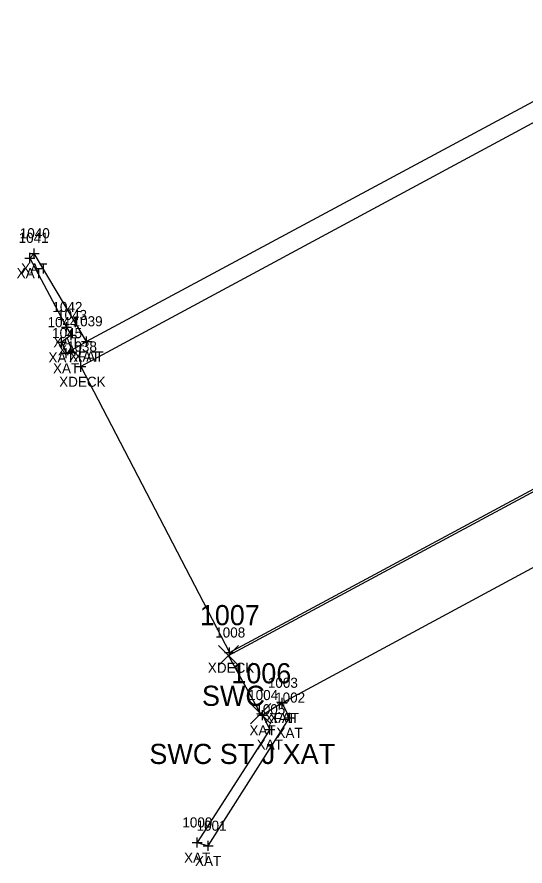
# Model space of a CAD drawing. Extents: x 1635588 to 1637550, y 621583 to 623638.
# Drawn here: x 1636318.7 to 1636369.1, y 623110.9 to 623195.1 of the extents above; entities that cross this region are included whole.
import ezdxf

# ---------------------------------------------------------------- set-up
doc = ezdxf.new("R2010")
doc.units = 0
for name, color, linetype in [('B_A', 7, 'Continuous'), ('B_I', 7, 'Continuous'), ('B_TIC', 7, 'Continuous'), ('BELB', 7, 'Continuous'), ('BF', 7, 'Continuous'), ('BSUBM', 7, 'Continuous'), ('R_A', 7, 'Continuous'), ('R_I', 7, 'Continuous'), ('R_TIC', 7, 'Continuous'), ('RSW', 7, 'Continuous')]:
    doc.layers.add(name, color=color, linetype=linetype)

msp = doc.modelspace()

# ---------------------------------------------------------------- linework, layer by layer
at = {"layer": 'B_TIC'}
for p, q in [((1636320.413, 623171.69), (1636320.489, 623171.69)), ((1636319.973, 623171.231), (1636320.049, 623171.231)), ((1636323.607, 623164.377), (1636323.683, 623164.377)), ((1636324.067, 623163.583), (1636324.142, 623163.583)), ((1636323.126, 623162.873), (1636323.201, 623162.873)), ((1636325.614, 623162.961), (1636325.69, 623162.961)), ((1636325.614, 623162.961), (1636325.69, 623162.961)), ((1636323.576, 623161.791), (1636323.651, 623161.791)), ((1636325.047, 623160.457), (1636325.122, 623160.457)), ((1636339.788, 623132.094), (1636339.864, 623132.094)), ((1636345.01, 623127.108), (1636345.086, 623127.108)), ((1636345.01, 623127.108), (1636345.086, 623127.108)), ((1636343.057, 623125.889), (1636343.132, 623125.889)), ((1636345.732, 623125.637), (1636345.807, 623125.637)), ((1636343.765, 623124.477), (1636343.84, 623124.477)), ((1636336.573, 623113.259), (1636336.649, 623113.259)), ((1636337.656, 623112.931), (1636337.732, 623112.931))]:
    msp.add_line(p, q, dxfattribs=at)
for points in [[(1636319.91, 623171.69), (1636320.91, 623171.69)], [(1636319.97, 623170.731), (1636319.97, 623171.731)], [(1636320.41, 623171.19), (1636320.41, 623172.19)], [(1636319.47, 623171.231), (1636320.47, 623171.231)], [(1636323.604, 623163.877), (1636323.604, 623164.877)], [(1636323.104, 623164.377), (1636324.104, 623164.377)], [(1636324.063, 623163.083), (1636324.063, 623164.083)], [(1636323.122, 623162.373), (1636323.122, 623163.373)], [(1636323.563, 623163.583), (1636324.563, 623163.583)], [(1636325.611, 623162.461), (1636325.611, 623163.461)], [(1636325.611, 623162.461), (1636325.611, 623163.461)], [(1636322.622, 623162.873), (1636323.622, 623162.873)], [(1636325.111, 623162.961), (1636326.111, 623162.961)], [(1636325.111, 623162.961), (1636326.111, 623162.961)], [(1636323.072, 623161.791), (1636324.072, 623161.791)], [(1636323.572, 623161.291), (1636323.572, 623162.291)], [(1636325.043, 623159.957), (1636325.043, 623160.957)], [(1636324.543, 623160.457), (1636325.543, 623160.457)], [(1636339.285, 623132.094), (1636340.285, 623132.094)], [(1636339.785, 623131.594), (1636339.785, 623132.594)], [(1636344.507, 623127.108), (1636345.507, 623127.108)], [(1636344.507, 623127.108), (1636345.507, 623127.108)], [(1636345.007, 623126.608), (1636345.007, 623127.608)], [(1636345.007, 623126.608), (1636345.007, 623127.608)], [(1636343.053, 623125.389), (1636343.053, 623126.389)], [(1636342.553, 623125.889), (1636343.553, 623125.889)], [(1636345.228, 623125.637), (1636346.228, 623125.637)], [(1636345.728, 623125.137), (1636345.728, 623126.137)], [(1636343.261, 623124.477), (1636344.261, 623124.477)], [(1636343.761, 623123.977), (1636343.761, 623124.977)], [(1636336.57, 623112.759), (1636336.57, 623113.759)], [(1636336.07, 623113.259), (1636337.07, 623113.259)], [(1636337.153, 623112.931), (1636338.153, 623112.931)], [(1636337.653, 623112.431), (1636337.653, 623113.431)]]:
    msp.add_lwpolyline(points, dxfattribs=at)
at = {"layer": 'BELB'}
msp.add_lwpolyline([(1636339.785, 623132.094), (1636403.647, 623166.459), (1636403.692, 623166.437), (1636388.517, 623194.676), (1636325.043, 623160.457), (1636339.785, 623132.094)], dxfattribs=at)
at = {"layer": 'BF'}
for points in [[(1636385.549, 623195.138), (1636325.611, 623162.961)], [(1636345.007, 623127.108), (1636404.932, 623159.451)]]:
    msp.add_lwpolyline(points, dxfattribs=at)
at = {"layer": 'BSUBM'}
for points in [[(1636325.611, 623162.961), (1636320.41, 623171.69), (1636319.97, 623171.231), (1636323.604, 623164.377), (1636324.063, 623163.583), (1636323.122, 623162.873), (1636323.572, 623161.791), (1636325.611, 623162.961)], [(1636336.57, 623113.259), (1636337.653, 623112.931), (1636345.728, 623125.637), (1636345.007, 623127.108), (1636343.053, 623125.889), (1636343.761, 623124.477), (1636336.57, 623113.259)]]:
    msp.add_lwpolyline(points, dxfattribs=at)
at = {"layer": 'R_TIC'}
for points in [[(1636338.684, 623130.815), (1636340.684, 623132.815)], [(1636340.684, 623130.815), (1636338.684, 623132.815)], [(1636341.862, 623125.048), (1636343.862, 623127.048)], [(1636343.862, 623125.048), (1636341.862, 623127.048)]]:
    msp.add_lwpolyline(points, dxfattribs=at)
at = {"layer": 'RSW'}
for points in [[(1636342.862, 623126.048), (1636339.684, 623131.815), (1636403.698, 623166.218)], [(1636343.053, 623125.889), (1636342.862, 623126.048)]]:
    msp.add_lwpolyline(points, dxfattribs=at)

# ---------------------------------------------------------------- texts
at = {"layer": 'B_A'}
for s, p in [('XAT', (1636318.675, 623169.231)), ('XAT', (1636319.115, 623169.69)), ('XAT', (1636322.309, 623162.377)), ('XAT', (1636322.768, 623161.583)), ('XAT', (1636321.827, 623160.873)), ('XFAT', (1636323.867, 623160.961)), ('XAT', (1636324.315, 623160.961)), ('XAT', (1636322.277, 623159.791)), ('XDECK', (1636322.886, 623158.457)), ('XDECK', (1636337.627, 623130.094)), ('XFAT', (1636343.263, 623125.108)), ('XAT', (1636343.711, 623125.108)), ('XAT', (1636341.758, 623123.889)), ('XAT', (1636344.433, 623123.637)), ('XAT', (1636342.466, 623122.477)), ('XAT', (1636335.274, 623111.259)), ('XAT', (1636336.358, 623110.931))]:
    msp.add_text(s, height=1, dxfattribs=at).set_placement(p)
at = {"layer": 'B_I'}
for s, p in [('1040', (1636318.981, 623173.19)), ('1041', (1636318.868, 623172.731)), ('1042', (1636322.218, 623165.877)), ('1043', (1636322.678, 623165.083)), ('1044', (1636321.737, 623164.373)), ('1039', (1636324.221, 623164.461)), ('1039', (1636324.221, 623164.461)), ('1045', (1636322.187, 623163.291)), ('1038', (1636323.658, 623161.957)), ('1008', (1636338.36, 623133.594)), ('1003', (1636343.582, 623128.608)), ('1003', (1636343.582, 623128.608)), ('1004', (1636341.628, 623127.389)), ('1002', (1636344.303, 623127.137)), ('1005', (1636342.336, 623125.977)), ('1000', (1636335.101, 623114.759)), ('1001', (1636336.511, 623114.431))]:
    msp.add_text(s, height=1, dxfattribs=at).set_placement(p)
at = {"layer": 'R_A'}
for s, p in [('SWC', (1636337.046, 623126.815)), ('SWC ST J XAT', (1636331.83, 623121.048))]:
    msp.add_text(s, height=2, dxfattribs=at).set_placement(p)
at = {"layer": 'R_I'}
for s, p in [('1007', (1636336.834, 623134.815)), ('1006', (1636339.956, 623129.048))]:
    msp.add_text(s, height=2, dxfattribs=at).set_placement(p)

doc.saveas('drawing.dxf')
